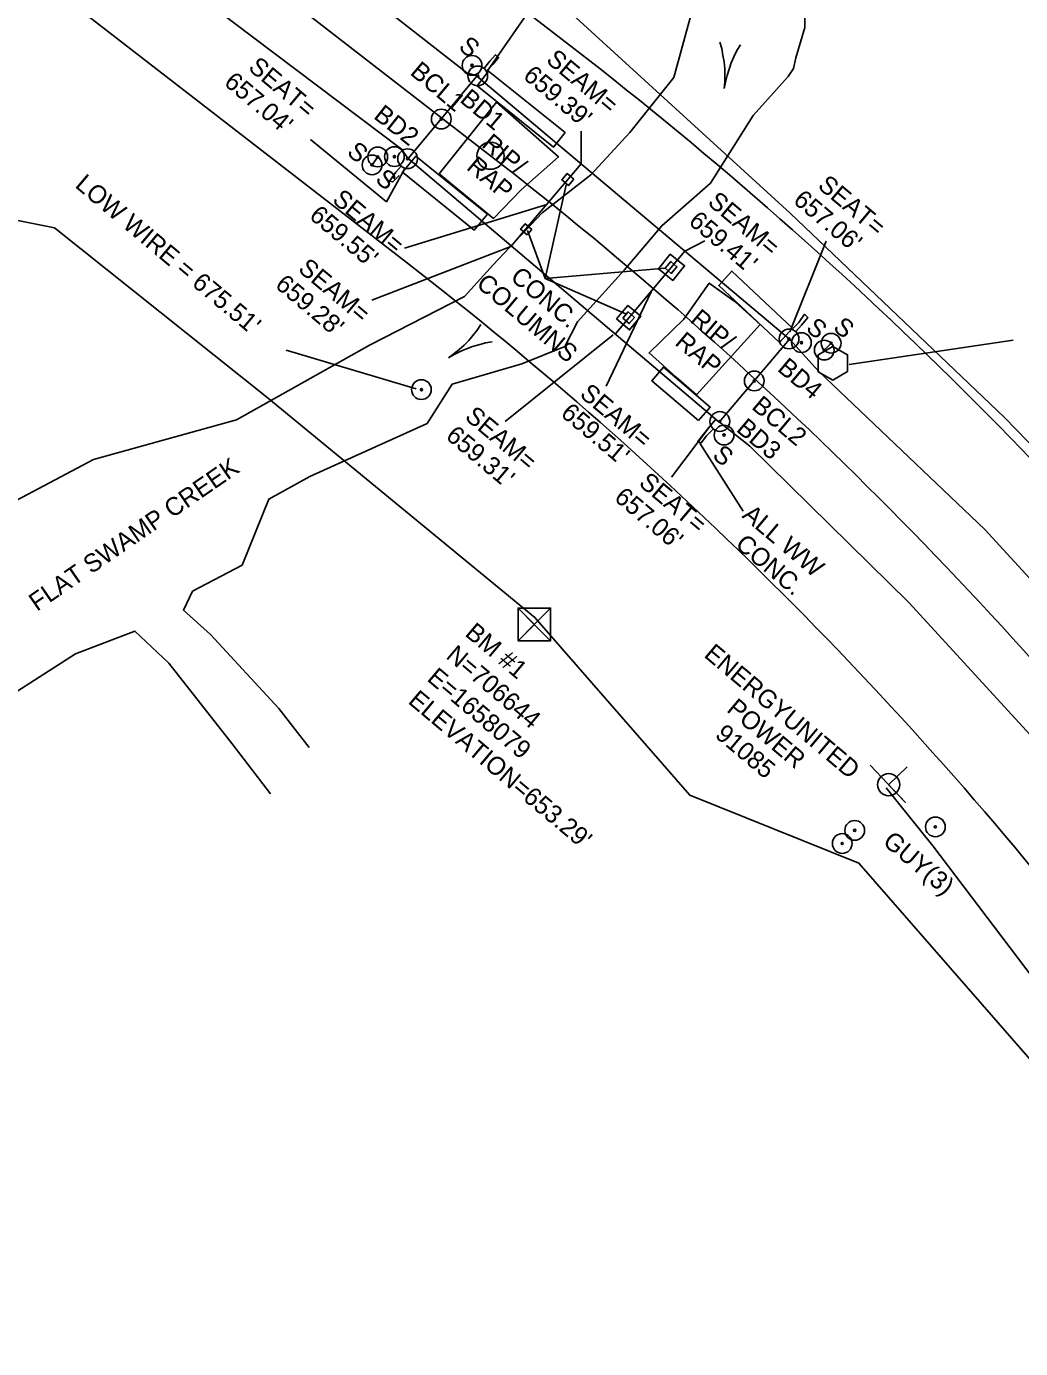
# Model space of a CAD drawing. Extents: x 1657485 to 1658542, y 706191 to 707067.
# Drawn here: x 1657966.6 to 1658186.2, y 706484 to 706776.1 of the extents above; entities that cross this region are included whole.
import ezdxf

# ---------------------------------------------------------------- set-up
doc = ezdxf.new("R2010")
doc.units = 0
for name, color, linetype in [('CTL Bench Mark Text', 7, 'Continuous'), ('CTL Supplemental Horizontal and Vertical Leader', 7, 'Continuous'), ('Exist Horizontal Alignment', 7, 'Continuous'), ('Exist Horizontal Alignment Point', 7, 'Continuous'), ('Exist Hydro Stream Flow Arrow CELL', 7, 'Continuous'), ('Exist Hydro Stream or Body of Water', 7, 'Continuous'), ('Exist Hydro Stream or Body of Water Text', 7, 'Continuous'), ('Exist Hydro Swamp or Marsh', 7, 'Continuous'), ('Exist Other Culture Anchor (Guy Wire) CELL', 7, 'Continuous'), ('Exist Other Culture Anchor (Guy Wire) Text', 7, 'Continuous'), ('Exist Other Culture Area Outline', 7, 'Continuous'), ('Exist Other Culture Area Outline Text', 7, 'Continuous'), ('Exist Other Culture Located Object CELL', 7, 'Continuous'), ('Exist Other Culture Located Object Leader', 7, 'Continuous'), ('Exist Other Culture Located Object Text', 7, 'Continuous'), ('Exist Other Culture Sign CELL', 7, 'Continuous'), ('Exist Other Culture Sign Text', 7, 'Continuous'), ('Exist Right of Way Line', 7, 'Continuous'), ('Exist Roads EOP', 7, 'Continuous'), ('Exist Roads EOP Other', 7, 'Continuous'), ('Exist Roads EOP Other Leader', 7, 'Continuous'), ('Exist Roads EOP Other Text', 7, 'Continuous'), ('Exist Structure Major Bridge Seam', 7, 'Continuous'), ('Exist Structure Major Bridge Seat Top Elevation', 7, 'Continuous'), ('Exist Structure Major Bridge WW', 7, 'Continuous'), ('Exist Structure Major Bridge WW Leader', 7, 'Continuous'), ('Exist Structure Major Bridge WW Text', 7, 'Continuous'), ('Exist Structure Major Deck Tunnel Box Culvert', 7, 'Continuous'), ('Exist Utilities Other Located Object CELL', 7, 'Continuous'), ('Exist Utilities Other Located Object Leader', 7, 'Continuous'), ('Exist Utilities Other Located Object Text', 7, 'Continuous'), ('Exist Utilities Power Joint Use Telephone CELL', 7, 'Continuous'), ('Exist Utilities Power Joint Use Telephone Text', 7, 'Continuous'), ('Exist Utilities Telephone UG FO SUE LOS C', 7, 'Continuous'), ('Exist Vegetation Woods Line', 7, 'Continuous'), ('Raster_Level_0', 7, 'Continuous')]:
    doc.layers.add(name, color=color, linetype=linetype)

msp = doc.modelspace()

# ---------------------------------------------------------------- linework, layer by layer
at = {"layer": 'CTL Supplemental Horizontal and Vertical Leader'}
msp.add_lwpolyline([(1658148.34, 706701.35), (1658184.52, 706706.77)], dxfattribs=at)
at = {"layer": 'Exist Horizontal Alignment'}
msp.add_line((1657821.54, 706939.11), (1658069.08, 706747.49), dxfattribs=at)
msp.add_arc((1657518.17, 706035.81), 900, 37.69406, 52.25664, dxfattribs=at)
at = {"layer": 'Exist Horizontal Alignment Point'}
msp.add_circle((1658069.08, 706747.49), 3, dxfattribs=at)
at = {"layer": 'Exist Hydro Stream Flow Arrow CELL'}
for p, q in [((1658121.36, 706767.3), (1658121.36, 706767.3)), ((1658063.99, 706705.57), (1658063.99, 706705.57))]:
    msp.add_line(p, q, dxfattribs=at)
for points in [[(1658119.73, 706772.55), (1658120.15, 706771.15), (1658120.43, 706769.67), (1658120.69, 706768.22), (1658120.82, 706766.78), (1658120.86, 706765.29), (1658120.84, 706763.8), (1658120.72, 706762.34)], [(1658124.27, 706771.97), (1658123.5, 706770.72), (1658122.86, 706769.36), (1658122.25, 706768.02), (1658121.76, 706766.65), (1658121.34, 706765.23), (1658120.98, 706763.78), (1658120.72, 706762.34)], [(1658066.95, 706710.2), (1658066.15, 706708.97), (1658065.2, 706707.81), (1658064.25, 706706.68), (1658063.23, 706705.65), (1658062.13, 706704.66), (1658060.97, 706703.72), (1658059.78, 706702.86)], [(1658069.43, 706706.36), (1658067.98, 706706.14), (1658066.53, 706705.75), (1658065.11, 706705.35), (1658063.75, 706704.85), (1658062.39, 706704.26), (1658061.05, 706703.59), (1658059.78, 706702.86)]]:
    msp.add_lwpolyline(points, dxfattribs=at)
at = {"layer": 'Exist Hydro Stream or Body of Water'}
for points in [[(1658124.22, 706972.45), (1658132.27, 706951.37), (1658136.16, 706946.2), (1658134.7, 706935.44), (1658128.81, 706912.12), (1658123.71, 706873.2), (1658111.95, 706830.1), (1658108.7, 706803.68), (1658113.38, 706778.75), (1658109.58, 706764.8), (1658099.83, 706752.59), (1658091.25, 706743.28), (1658080.45, 706734.89), (1658069.68, 706723.38), (1658063.35, 706716.36), (1658042.47, 706705.75), (1658012.94, 706689.18), (1657981.36, 706680.35), (1657950.92, 706664.28), (1657936.29, 706648.78), (1657910.94, 706618)], [(1658138.27, 706788.84), (1658138.48, 706775.79), (1658136.51, 706769.14), (1658136.02, 706766.73), (1658134.86, 706764.97), (1658127.09, 706756.38), (1658117.67, 706741.42), (1658106.9, 706732.01), (1658098.57, 706722.2), (1658088.3, 706710.83), (1658085.52, 706705.33), (1658075.97, 706701.52), (1658060.61, 706697.02), (1658055.07, 706688.37), (1658029.15, 706676.66), (1658020.11, 706671.64), (1658014.2, 706657.03), (1658003.24, 706651.26), (1658001.22, 706647.07), (1658007.2, 706641.7), (1658022.31, 706625.36), (1658029.03, 706616.76)], [(1658020.44, 706606.5), (1658012.04, 706617.54), (1657998.03, 706635.41), (1657990.51, 706642.47), (1657977.41, 706637.46), (1657955.29, 706623.31), (1657936.23, 706597.28)]]:
    msp.add_lwpolyline(points, dxfattribs=at)
at = {"layer": 'Exist Hydro Swamp or Marsh'}
msp.add_line((1658078.76, 706643.95), (1658078.76, 706643.95), dxfattribs=at)
msp.add_lwpolyline([(1658075.16, 706647.54), (1658082.35, 706647.54), (1658082.35, 706640.35), (1658075.16, 706640.35)], close=True, dxfattribs=at)
for points in [[(1658082.35, 706647.54), (1658075.16, 706640.35), (1658078.75, 706643.95), (1658082.35, 706640.35), (1658075.16, 706647.54)], [(1658078.75, 706643.95), (1658082.35, 706647.54), (1658075.16, 706647.54), (1658078.75, 706643.95)], [(1658078.75, 706643.95), (1658075.16, 706640.35), (1658082.35, 706640.35), (1658078.75, 706643.95)]]:
    msp.add_lwpolyline(points, dxfattribs=at)
at = {"layer": 'Exist Other Culture Anchor (Guy Wire) CELL'}
for centre, radius in [((1658167.35, 706599.22), 2.18), ((1658149.52, 706598.44), 2.18), ((1658149.52, 706598.44), 0.24), ((1658167.35, 706599.22), 0.24), ((1658146.77, 706595.55), 2.18), ((1658146.77, 706595.55), 0.24)]:
    msp.add_circle(centre, radius, dxfattribs=at)
at = {"layer": 'Exist Other Culture Anchor (Guy Wire) Text'}
msp.add_line((1658117.43, 706687.59), (1658118.84, 706689.26), dxfattribs=at)
at = {"layer": 'Exist Other Culture Area Outline'}
for points in [[(1658057.76, 706743.51), (1658069.77, 706733.64), (1658075.83, 706739.97), (1658084.08, 706747.27), (1658070.39, 706759.3)], [(1658128.63, 706710.23), (1658123.09, 706715.2), (1658117.41, 706719.36), (1658111.78, 706711.39), (1658104.12, 706703.92), (1658110.07, 706698.58), (1658114.61, 706694.65)]]:
    msp.add_lwpolyline(points, close=True, dxfattribs=at)
at = {"layer": 'Exist Other Culture Located Object CELL'}
for centre, radius in [((1658066.26, 706765.13), 2.18), ((1658066.26, 706765.13), 0.24), ((1658058.21, 706755.59), 2.18), ((1658058.21, 706755.59), 0.24), ((1658050.77, 706746.84), 2.18), ((1658050.77, 706746.84), 0.24), ((1658135.02, 706707.01), 2.18), ((1658135.02, 706707.01), 0.24), ((1658127.33, 706697.73), 2.18), ((1658127.33, 706697.73), 0.24), ((1658119.74, 706688.78), 2.18), ((1658119.74, 706688.78), 0.24)]:
    msp.add_circle(centre, radius, dxfattribs=at)
at = {"layer": 'Exist Other Culture Located Object Leader'}
for p, q in [((1658068.41, 706766.22), (1658082.16, 706786.08)), ((1658089.13, 706745.72), (1658089.13, 706752.91)), ((1658081.55, 706736.72), (1658050.06, 706727.05)), ((1658073.57, 706727.42), (1658042.83, 706715.58)), ((1658112.01, 706726.41), (1658116.41, 706728.72)), ((1658135.19, 706708.56), (1658143.19, 706728.63)), ((1658104.6, 706717.45), (1658094.63, 706696.58)), ((1658096.2, 706707.9), (1658072.31, 706688.8)), ((1658117.43, 706687.59), (1658109.06, 706676.49))]:
    msp.add_line(p, q, dxfattribs=at)
msp.add_lwpolyline([(1658050.08, 706744.53), (1658046.08, 706737.33), (1658029.3, 706751.08)], dxfattribs=at)
at = {"layer": 'Exist Other Culture Sign CELL'}
for p, q in [((1658044.16, 706747.23), (1658042.91, 706745.47)), ((1658142.79, 706704.54), (1658144.32, 706706.07))]:
    msp.add_line(p, q, dxfattribs=at)
for centre, radius in [((1658065, 706767.45), 2.18), ((1658065, 706767.45), 0.24), ((1658042.91, 706745.47), 2.18), ((1658044.16, 706747.23), 2.18), ((1658044.16, 706747.23), 0.24), ((1658047.85, 706747.3), 2.18), ((1658047.85, 706747.3), 0.24), ((1658042.91, 706745.47), 0.24), ((1658137.76, 706706.21), 2.18), ((1658137.76, 706706.21), 0.24), ((1658142.79, 706704.55), 2.18), ((1658142.79, 706704.54), 2.18), ((1658144.32, 706706.07), 2.18), ((1658144.32, 706706.07), 0.24), ((1658142.79, 706704.55), 0.24), ((1658142.79, 706704.54), 0.24), ((1658120.66, 706685.79), 2.18), ((1658120.66, 706685.79), 0.24)]:
    msp.add_circle(centre, radius, dxfattribs=at)
at = {"layer": 'Exist Right of Way Line'}
for p, q in [((1657839.91, 706962.84), (1658087.45, 706771.22)), ((1657803.18, 706915.39), (1658050.72, 706723.77))]:
    msp.add_line(p, q, dxfattribs=at)
for radius in [930, 870]:
    msp.add_arc((1657518.17, 706035.81), radius, 37.69406, 52.25664, dxfattribs=at)
at = {"layer": 'Exist Roads EOP'}
for points in [[(1657829.19, 706948.18), (1657868.22, 706918.15), (1657908.36, 706887.05), (1657947.4, 706856.64), (1657986.78, 706825.79), (1658025.82, 706795.57), (1658063.85, 706765.84), (1658066.09, 706765.17)], [(1657814.35, 706929.59), (1657853.7, 706899.35), (1657893.53, 706868.5), (1657933.27, 706838.23), (1657972.18, 706807.62), (1658012.04, 706777.15), (1658049.42, 706748.92), (1658050.79, 706746.94)], [(1658135.14, 706707), (1658141.59, 706699.82), (1658178.28, 706664.89), (1658211.96, 706628.22), (1658243.31, 706589.35), (1658273.06, 706549.33), (1658301.37, 706507.62), (1658321.82, 706472.94), (1658330.3, 706457.49)], [(1658119.64, 706688.66), (1658126.38, 706683.34), (1658161.45, 706648.81), (1658193.94, 706613.4), (1658224.34, 706575.92), (1658253.66, 706536.49), (1658281.8, 706494.3), (1658301.56, 706461.25), (1658312.18, 706441.62)]]:
    msp.add_lwpolyline(points, dxfattribs=at)
at = {"layer": 'Exist Roads EOP Other'}
for points in [[(1658068.65, 706766.15), (1658085.54, 706752.61), (1658082.98, 706749.35), (1658066.1, 706762.9)], [(1658049.64, 706743.84), (1658065.43, 706731.04), (1658068.4, 706734.6), (1658052.6, 706747.4)], [(1658087.45, 706742.33), (1658085.98, 706743.54), (1658084.84, 706742.15), (1658086.32, 706740.95)], [(1658078.18, 706731.23), (1658076.74, 706732.47), (1658075.71, 706731.27), (1658077.14, 706730.04)], [(1658106.19, 706722.47), (1658108.77, 706725.72), (1658111.95, 706723.2), (1658109.37, 706719.95)], [(1658107.66, 706722.69), (1658108.92, 706724.13), (1658110.27, 706722.96), (1658109.01, 706721.51)], [(1658135.78, 706709.4), (1658122.36, 706722), (1658119.5, 706718.84), (1658132.93, 706706.24)], [(1658096.91, 706711.44), (1658099.41, 706714.44), (1658102.3, 706712.02), (1658099.8, 706709.03)], [(1658098.31, 706711.61), (1658099.47, 706712.97), (1658100.88, 706711.76), (1658099.72, 706710.41)], [(1658115, 706689.01), (1658104.7, 706697.79), (1658107.27, 706700.75), (1658117.58, 706691.97)]]:
    msp.add_lwpolyline(points, close=True, dxfattribs=at)
at = {"layer": 'Exist Roads EOP Other Leader'}
for p in [(1658085.78, 706741.07), (1658077.25, 706730.94), (1658107.69, 706722.63), (1658099.13, 706712.46)]:
    msp.add_line(p, (1658081.17, 706720.39), dxfattribs=at)
at = {"layer": 'Exist Structure Major Bridge Seam'}
for p, q in [((1658089.13, 706745.72), (1658073.57, 706727.42)), ((1658096.61, 706708.09), (1658112.01, 706726.41))]:
    msp.add_line(p, q, dxfattribs=at)
at = {"layer": 'Exist Structure Major Bridge WW'}
for points in [[(1658067.74, 706766.91), (1658068.96, 706768.36), (1658070.15, 706769.8), (1658070.86, 706769.23), (1658069.67, 706767.72), (1658068.37, 706766.4)], [(1658048.9, 706743.13), (1658047.46, 706741.71), (1658046.75, 706741.89), (1658048.13, 706743.88), (1658049.31, 706745.21)], [(1658136.52, 706708.68), (1658137.75, 706710.08), (1658139.18, 706711.74), (1658138.46, 706712.46), (1658137.15, 706710.66), (1658135.86, 706709.32)], [(1658118.2, 706687), (1658116.78, 706685.6), (1658115.6, 706684.03), (1658114.87, 706684.39), (1658116.17, 706686.05), (1658117.36, 706687.56)]]:
    msp.add_lwpolyline(points, dxfattribs=at)
at = {"layer": 'Exist Structure Major Bridge WW Leader'}
msp.add_line((1658115.32, 706684.02), (1658124.92, 706669), dxfattribs=at)
at = {"layer": 'Exist Structure Major Deck Tunnel Box Culvert'}
msp.add_lwpolyline([(1658066.08, 706765.09), (1658135.11, 706707), (1658119.58, 706688.64), (1658050.89, 706746.86)], close=True, dxfattribs=at)
at = {"layer": 'Exist Utilities Other Located Object CELL'}
for radius in [2.18, 0.24]:
    msp.add_circle((1658053.82, 706695.82), radius, dxfattribs=at)
at = {"layer": 'Exist Utilities Other Located Object Leader'}
msp.add_line((1658052.63, 706696.03), (1658023.91, 706704.54), dxfattribs=at)
at = {"layer": 'Exist Utilities Power Joint Use Telephone CELL'}
msp.add_line((1658157.03, 706608.55), (1658157.03, 706608.55), dxfattribs=at)
msp.add_lwpolyline([(1658152.92, 706612.84), (1658160.74, 706604.63), (1658157.01, 706608.54), (1658161.09, 706612.45)], dxfattribs=at)
msp.add_circle((1658157.03, 706608.56), 2.45, dxfattribs=at)
at = {"layer": 'Exist Utilities Telephone UG FO SUE LOS C'}
msp.add_lwpolyline([(1658156.48, 706607.81), (1658166.81, 706595.04), (1658206, 706543.25), (1658248.05, 706509.25), (1658268.32, 706498.9), (1658281.54, 706478.53), (1658326.28, 706409.17)], dxfattribs=at)
at = {"layer": 'Exist Vegetation Woods Line'}
for points in [[(1658135.28, 706734.78), (1658006.85, 706852.11), (1657978.27, 706896.38), (1657901.37, 706954.71), (1657820.9, 707012.72)], [(1657933.82, 706739.37), (1657972.73, 706731.57), (1658019.66, 706694.17)], [(1658341.34, 706528.45), (1658323.21, 706523.36), (1658263.56, 706606.39), (1658182.59, 706689.69), (1658135.28, 706734.78)], [(1658019.66, 706694.17), (1658078.9, 706645.5), (1658113.07, 706606.19), (1658150.47, 706591.18), (1658218.07, 706513.76), (1658255.76, 706492.71), (1658285.88, 706434.99)]]:
    msp.add_lwpolyline(points, dxfattribs=at)
at = {"layer": 'Raster_Level_0'}
msp.add_line((1658144.7, 706701.65), (1658144.7, 706701.65), dxfattribs=at)
msp.add_lwpolyline([(1658141.47, 706703.52), (1658144.72, 706705.33), (1658147.97, 706703.54), (1658147.92, 706699.82), (1658144.67, 706697.93), (1658141.47, 706699.74)], close=True, dxfattribs=at)

# ---------------------------------------------------------------- texts
at = {"layer": 'CTL Bench Mark Text'}
for s, p in [('BM #1', (1658063.21, 706641.61)), ('N=706644  ', (1658059.02, 706636.64)), ('E=1658079', (1658054.83, 706631.67)), ("ELEVATION=653.29'", (1658050.65, 706626.69))]:
    msp.add_text(s, height=4, rotation=319.9162, dxfattribs=at).set_placement(p)
at = {"layer": 'Exist Hydro Stream or Body of Water Text'}
msp.add_text('FLAT SWAMP CREEK', height=4, rotation=34.5601, dxfattribs=at).set_placement((1657968.88, 706646.73))
at = {"layer": 'Exist Other Culture Anchor (Guy Wire) Text'}
msp.add_text('GUY(3)', height=4, rotation=319.9162, dxfattribs=at).set_placement((1658155.49, 706595.54))
at = {"layer": 'Exist Other Culture Area Outline Text'}
for s, p in [('RIP/', (1658066.89, 706749.64)), ('RAP', (1658063.54, 706744.63)), ('RIP/', (1658112.94, 706710.89)), ('RAP', (1658109.58, 706705.87))]:
    msp.add_text(s, height=4, rotation=319.9162, dxfattribs=at).set_placement(p)
at = {"layer": 'Exist Other Culture Located Object Text'}
for s, rotation, p in [('BCL1', 319.9162, (1658051.09, 706765.6)), ('BD1', 319.9162, (1658062.08, 706759.54)), ('BD2', 321.5501, (1658043.03, 706755.93)), ('BD4', 319.9162, (1658132.24, 706700.13)), ('BCL2', 319.9162, (1658126.53, 706691.74)), ('BD3', 319.9162, (1658123.14, 706686.78))]:
    msp.add_text(s, height=4, rotation=rotation, dxfattribs=at).set_placement(p)
at = {"layer": 'Exist Other Culture Sign Text'}
for p in [(1658061.81, 706771.21), (1658037.13, 706747.93), (1658043.4, 706741.93), (1658138.53, 706709.03), (1658144.55, 706709.17), (1658117.86, 706680.93)]:
    msp.add_text('S', height=4, rotation=319.9162, dxfattribs=at).set_placement(p)
at = {"layer": 'Exist Roads EOP Other Text'}
for s, p in [('COLUMNS', (1658065.69, 706718.76)), ('CONC.', (1658073.22, 706720.27))]:
    msp.add_text(s, height=4, rotation=319.9162, dxfattribs=at).set_placement(p)
at = {"layer": 'Exist Structure Major Bridge Seat Top Elevation'}
for s, p in [('SEAM=', (1658081.14, 706768.31)), ('SEAT=', (1658015.34, 706766.63)), ("659.39'", (1658076.05, 706764.75)), ("657.04'", (1658009.98, 706763.3)), ('SEAT=', (1658141.14, 706740.52)), ('SEAM=', (1658033.89, 706737.39)), ('SEAM=', (1658116.82, 706736.87)), ("657.06'", (1658135.71, 706737.25)), ("659.55'", (1658028.8, 706733.83)), ("659.41'", (1658112.6, 706732.58)), ('SEAM=', (1658026.36, 706722.13)), ("659.28'", (1658021.27, 706718.57)), ('SEAM=', (1658088.57, 706694.45)), ('SEAM=', (1658063.18, 706689.45)), ("659.51'", (1658084.35, 706690.17)), ("659.31'", (1658058.96, 706685.16)), ('SEAT=', (1658101.6, 706674.83)), ("657.06'", (1658096.17, 706671.55))]:
    msp.add_text(s, height=4, rotation=319.9162, dxfattribs=at).set_placement(p)
at = {"layer": 'Exist Structure Major Bridge WW Text'}
for s, p in [('ALL WW', (1658124.45, 706667.72)), ('CONC.', (1658122.9, 706661.18))]:
    msp.add_text(s, height=4, rotation=319.9162, dxfattribs=at).set_placement(p)
at = {"layer": 'Exist Utilities Other Located Object Text'}
msp.add_text("LOW WIRE = 675.51'", height=4, rotation=319.9162, dxfattribs=at).set_placement((1657977.08, 706740.69))
at = {"layer": 'Exist Utilities Power Joint Use Telephone Text'}
for s, p in [('ENERGYUNITED', (1658116, 706636.94)), ('POWER', (1658121.03, 706624.86)), ('91085', (1658118.45, 706619.2))]:
    msp.add_text(s, height=4, rotation=319.9162, dxfattribs=at).set_placement(p)

doc.saveas('drawing.dxf')
